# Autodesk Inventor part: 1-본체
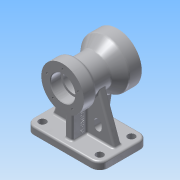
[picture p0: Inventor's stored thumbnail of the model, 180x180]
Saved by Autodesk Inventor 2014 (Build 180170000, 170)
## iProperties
Created: 2015-08
Part Number: 1-본체
Material: 알루미늄 6061
Document SubType Name: Modeling
Designer: study
Density: 2.71 g/cm^3
Appearance: 알루미늄 - 평지
Mass: 1062.79 g
Surface Area: 749.652 cm^2
Volume: 392.172 cm^3
Author: study
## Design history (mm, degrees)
sketch "스케치1"
  geometry: L1 (-61, -40)-(61, -40); L2 (61, -40)-(61, 40); L3 (61, 40)-(-61, 40); L4 (-61, 40)-(-61, -40); L5 (-61, -40)-(61, 40); L6 (61, -40)-(-61, 40); 1 further point
  constraints: 12 end point, 2 midpoint, 2 parallel, 1 horizontal, 1 perpendicular
  dimensions: "d0" = 122 distance of L2.end L3.end; "d1" = 80 distance of L1.end L2.end
extrude "돌출1" new body sketch "스케치1" distance "d2" = 12; taper "d3" = 0 deg
fillet "모깎기1" dims "d4" = 14
sketch "스케치2"
  geometry: L1 (-40, 90)-(50, 90); L2 (-40, 90)-(-40, 125); L3 (-40, 125)-(-20, 125); L4 (-20, 125)-(-14.804, 116); L5 (-14.804, 116)-(13.315, 116); L6 (13.315, 116)-(30, 130); L7 (30, 130)-(50, 130); L8 (50, 130)-(50, 90); L9 (-26, 0)-(26, 0) reference; 2 further points
  constraints: 16 end point, 3 perpendicular, 2 parallel, 1 horizontal, 1 vertical alignment
  dimensions: "d5" = 52 diameter of L5 L1; "d6" = 70 diameter of L3 L1; "d7" = 80 diameter of L7 L1; "d8" = 20 distance of L2.end L3.end; "d9" = 20 distance of L6.end L7.end; "d10" = 90 distance of L1.start L1.end; "d11" = 40 deg angle of L6 L5; "d12" = 60 deg angle of L5 L4; "d13" = 90 distance between parallel lines of L9 L1
revolve "회전1" sketch "스케치2" stored, may be unused: angle "d14" = 90 deg
sketch "스케치3"
  geometry: L1 (-40, 12)-(-26, 12) reference; L2 (-26, 12)-(26, 12) reference; L3 (26, 12)-(40, 12) reference; L4 (-30, 12)-(-30, 71.689); L5 (-30, 71.689)-(40.525, 71.689); L6 (40.525, 71.689)-(30, 12); L7 (-40, 12)-(-40, 0) reference; L8 (40, 0)-(40, 12) reference; L9 (30, 12)-(-30, 12); 1 further point
  constraints: 8 end point, 2 point on line, 1 collinear, 1 parallel, 1 perpendicular
  dimensions: "d15" = 10 distance between parallel lines of L7 L4; "d16" = 10 distance from line of L8 L6.end; "d17" = 80 deg angle of L3 L6; "d18" = 59.6894 distance between parallel lines of L5 L3
extrude "돌출2" join sketch "스케치3" stored distance "d19" = 12; taper "d20" = 0 deg
sketch "스케치4"
  geometry: L1 (-61, 12)-(-47, 12) reference; L2 (-47, 12)-(47, 12) reference; L3 (47, 12)-(61, 12) reference; L4 (-51, 12)-(-21.882, 92); L5 (-21.882, 92)-(21.882, 92); L6 (21.882, 92)-(51, 12); L7 (61, 0)-(61, 12) reference; L8 (-61, 12)-(-61, 0) reference; L9 (-51, 12)-(51, 12); 1 further point
  constraints: 8 end point, 2 point on line, 1 collinear, 1 horizontal
  dimensions: "d21" = 10 distance from line of L7 L6.end; "d22" = 10 distance from line of L8 L4.start; "d23" = 70 deg angle of L2 L6; "d24" = 70 deg angle of L2 L4; "d25" = 80 distance between parallel lines of L3 L5
extrude "돌출3" join sketch "스케치4" stored distance "d26" = 12; taper "d27" = 0 deg
sketch "스케치5"
  geometry: L1 (6, -12)-(51, -12) reference; L2 (6, -64.702)-(6, -12) reference; L3 (18, -30)-(18, -36); L4 (30, -36)-(30, -30); A1 r 26 centre (0, -90) between (25.091, -83.185) and (6, -64.702) reference; A2 r 6 centre (24, -36) between (18, -36) and (30, -36); A3 r 6 centre (24, -30) between (30, -30) and (18, -30); 2 further points
  constraints: 4 end point, 4 point on circle, 4 tangent, 2 centre point, 2 parallel
  dimensions: "d28" = 12 distance between parallel lines of L4 L3; "d29" = 18 dimension on A2 A3; "d30" = 24 horizontal distance of A1.centre A3.centre; "d31" = 18 distance from line of L1 A3.centre
extrude "돌출4" cut sketch "스케치5" stored distance "d32" = 12; taper "d33" = 0 deg
sketch "스케치6"
  geometry: A1 r 14 centre (47, 26) between (61, 26) and (47, 40) reference; A2 r 14 centre (-47, 26) between (-47, 40) and (-61, 26) reference; A3 r 14 centre (-47, -26) between (-61, -26) and (-47, -40) reference; A4 r 14 centre (47, -26) between (47, -40) and (61, -26) reference; 5 further points
  constraints: 4 coincident
hole "구멍1" sketch "스케치6" at (-47, 26), (-47, -26), (47, -26), (47, 26) diameter "d34" = 12; stored, may be unused: countersink angle "d38" = 90 deg, drill point angle "d40" = 118 deg; dims "d35" = 6, "d36" = 4, "d37" = 2, "d39" = 8
hole "구멍2" diameter "d43" = 38; stored, may be unused: countersink angle "d47" = 90 deg, drill point angle "d49" = 0 deg; dims "d41" = 10, "d42" = 10, "d44" = 6, "d45" = 52, "d46" = 20, "d48" = 23
hole "구멍3" diameter "d52" = 32; stored, may be unused: countersink angle "d56" = 90 deg, drill point angle "d58" = 0 deg; dims "d50" = 10, "d51" = 10, "d53" = 6, "d54" = 40, "d55" = 17, "d57" = 23
sketch "스케치7"
  geometry: C1 r 26 at (0, 0) reference; 2 further points
  constraints: 1 vertical alignment
  dimensions: "d59" = 33 distance of point (0, -33) C1.centre
hole "구멍4" sketch "스케치7" at (0, -33) diameter "d60" = 3.242; stored, may be unused: countersink angle "d64" = 90 deg, drill point angle "d66" = 118 deg; dims "d61" = 10, "d62" = 40, "d63" = 17, "d65" = 13
sketch "스케치8"
  geometry: C1 r 20 at (0, 0) reference; 2 further points
  constraints: 1 vertical alignment
  dimensions: "d70" = 27 distance of C1.centre point (0, 27)
hole "구멍5" sketch "스케치8" at (0, 27) diameter "d71" = 3.242; stored, may be unused: countersink angle "d75" = 90 deg, drill point angle "d77" = 118 deg; dims "d72" = 10, "d73" = 40, "d74" = 17, "d76" = 13
sketch "스케치9"
  geometry: L1 (-55.518, -30)-(-12, -30) reference; L2 (-12, -6)-(-12, -30) reference; 2 further points
  constraints: 1 other
  dimensions: "d81" = 16 distance from line of point (-36, -14) L1; "d82" = 24 distance from line of L2 point (-36, -14)
feature "엠보싱1" sketch "스케치9" dims "d0" = 122, "d1" = 80, "d83" = 0.5, "d84" = 0
fillet "모깎기2" dims "d85" = 5, "d86" = 0.3
fillet "모깎기3" dims "d87" = 3
fillet "모깎기4" dims "d88" = 3
chamfer "모따기1" distance "d89" = 1; stored, may be unused: second distance "d90" = 2, angle "d91" = 45 deg
node "솔리드1"
mirror "대칭1"
pattern_circular "원형 패턴1" dims angle "d68" = 360 deg
pattern_circular "원형 패턴2" dims angle "d79" = 360 deg
